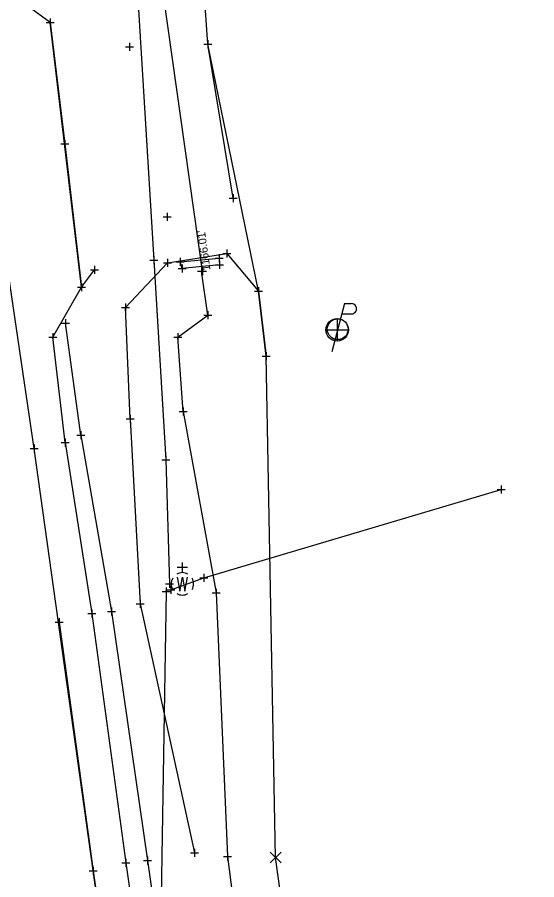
# Model space of a CAD drawing. Extents: x 2324380 to 2325559, y 691096 to 693386.
# Drawn here: x 2325205.9 to 2325270.8, y 691550.8 to 691658.5 of the extents above; entities that cross this region are included whole.
import ezdxf

# ---------------------------------------------------------------- set-up
doc = ezdxf.new("R2010")
doc.units = 0
for name, color, linetype in [('DR_X_Elev_Flow', 7, 'Continuous'), ('DR_X_Headwall', 7, 'Continuous'), ('DR_X_Storm_Sewer', 7, 'Continuous'), ('PM_X_Transverse_Line', 7, 'Continuous'), ('PV_X_Driveway', 7, 'Continuous'), ('PV_X_EOP', 7, 'Continuous'), ('PV_X_Shoulder_Aggregate', 7, 'Continuous'), ('SC_Scratch1', 7, 'Continuous'), ('SV_X_Control_Cells_Found', 7, 'Continuous'), ('SV_X_Random_Point', 7, 'Continuous'), ('SV_X_Shot_Marker', 7, 'Continuous'), ('SV_X_Terrain_Boundary', 7, 'Continuous'), ('SV_X_Toe_of_Slope', 7, 'Continuous'), ('SV_X_Top_of_Bank', 7, 'Continuous'), ('UT_X_Electric_Cells', 7, 'Continuous'), ('UT_X_Water', 7, 'Continuous'), ('UT_X_Water_Cells', 7, 'Continuous')]:
    doc.layers.add(name, color=color, linetype=linetype)

msp = doc.modelspace()

# ---------------------------------------------------------------- linework, layer by layer
at = {"layer": 'DR_X_Elev_Flow'}
for p, q in [((2325229.09, 691627.27), (2325229.09, 691626.27)), ((2325228.59, 691626.77), (2325229.59, 691626.77)), ((2325229.09, 691626.77), (2325229.09, 691626.77))]:
    msp.add_line(p, q, dxfattribs=at)
at = {"layer": 'DR_X_Headwall'}
msp.add_lwpolyline([(2325231.15, 691628.41), (2325231.2, 691627.58), (2325226.52, 691627.12), (2325226.3, 691627.96)], close=True, dxfattribs=at)
at = {"layer": 'DR_X_Storm_Sewer'}
msp.add_line((2325229.09, 691626.77), (2325217.52, 691708.33), dxfattribs=at)
at = {"layer": 'PM_X_Transverse_Line'}
for points in [[(2325208.03, 691604.62), (2325194.77, 691694.59), (2325190.22, 691721.35), (2325186.04, 691748.47), (2325180.66, 691777.72), (2325175.44, 691810.81), (2325170.12, 691836.61), (2325164.91, 691862.73), (2325159.59, 691887.99), (2325154.32, 691913.69), (2325148, 691940.38), (2325141.01, 691970.75), (2325134.25, 691997.6), (2325126.61, 692026.24), (2325119.99, 692049.57), (2325112.24, 692077.64)], [(2325211.18, 691582.94), (2325215.4, 691551.9), (2325219.83, 691521.11), (2325223.47, 691495.08), (2325231.47, 691437.85), (2325235.46, 691407.56), (2325239.99, 691376.18), (2325243.53, 691349.64), (2325247.32, 691323.83), (2325208.03, 691604.62)]]:
    msp.add_lwpolyline(points, dxfattribs=at)
at = {"layer": 'PV_X_Driveway'}
for p, q in [((2325210.03, 691657.83), (2325211.87, 691642.67)), ((2325232.92, 691635.92), (2325229.73, 691655.12)), ((2325211.87, 691642.67), (2325213.96, 691624.8)), ((2325213.96, 691624.8), (2325215.58, 691626.95))]:
    msp.add_line(p, q, dxfattribs=at)
at = {"layer": 'PV_X_EOP'}
for points in [[(2325211.92, 691605.39), (2325210.37, 691618.55), (2325213.96, 691624.8), (2325210.03, 691657.83), (2325203.56, 691662.57), (2325202.33, 691668.93), (2325198.24, 691695.48), (2325193.91, 691721.99), (2325189.38, 691749.91), (2325184.43, 691778.63), (2325178.88, 691811.26), (2325173.94, 691837.31), (2325168.71, 691863.96), (2325163.82, 691888.36), (2325158.39, 691913.65), (2325152.29, 691941.35), (2325145.12, 691971.33), (2325138.19, 691997.21), (2325140.74, 692005.58), (2325134.93, 692029.17), (2325130.4, 692046.73), (2325123.25, 692051.46), (2325115.82, 692078.51)], [(2325211.92, 691605.39), (2325215.25, 691584.03), (2325219.49, 691552.88), (2325224.03, 691521.29), (2325227.5, 691495.17), (2325231.22, 691468.2), (2325235.39, 691438.82), (2325239.64, 691407.75), (2325243.92, 691377.46), (2325247.9, 691350.92), (2325251.27, 691324.43)]]:
    msp.add_lwpolyline(points, dxfattribs=at)
at = {"layer": 'PV_X_Shoulder_Aggregate'}
for points in [[(2325213.88, 691606.29), (2325211.98, 691620.27)], [(2325213.88, 691606.29), (2325217.7, 691584.26), (2325222.21, 691553.19), (2325226.65, 691521.82), (2325230.46, 691495.18), (2325234, 691469.07), (2325237.48, 691439.41), (2325242.52, 691408.67), (2325246.13, 691377.89), (2325250.02, 691351.19), (2325253.28, 691324.76)]]:
    msp.add_lwpolyline(points, dxfattribs=at)
at = {"layer": 'SV_X_Control_Cells_Found'}
for p, q in [((2325245.89, 691620.86), (2325245.89, 691618.04)), ((2325244.48, 691619.45), (2325247.3, 691619.45))]:
    msp.add_line(p, q, dxfattribs=at)
msp.add_circle((2325245.89, 691619.45), 1.41, dxfattribs=at)
at = {"layer": 'SV_X_Random_Point'}
for p, q in [((2325237.54, 691552.88), (2325238.88, 691554.21)), ((2325237.54, 691554.21), (2325238.88, 691552.88))]:
    msp.add_line(p, q, dxfattribs=at)
at = {"layer": 'SV_X_Shot_Marker'}
for p, q in [((2325209.53, 691657.83), (2325210.53, 691657.83)), ((2325209.53, 691657.83), (2325210.53, 691657.83)), ((2325210.03, 691658.33), (2325210.03, 691657.33)), ((2325210.03, 691658.33), (2325210.03, 691657.33)), ((2325210.03, 691657.83), (2325210.03, 691657.83)), ((2325210.03, 691657.83), (2325210.03, 691657.83)), ((2325219.96, 691655.3), (2325219.96, 691654.3)), ((2325229.23, 691655.12), (2325230.23, 691655.12)), ((2325229.73, 691655.62), (2325229.73, 691654.62)), ((2325229.73, 691655.12), (2325229.73, 691655.12)), ((2325219.46, 691654.8), (2325220.46, 691654.8)), ((2325219.96, 691654.8), (2325219.96, 691654.8)), ((2325211.37, 691642.67), (2325212.37, 691642.67)), ((2325211.87, 691643.17), (2325211.87, 691642.17)), ((2325211.87, 691642.67), (2325211.87, 691642.67)), ((2325232.42, 691635.92), (2325233.42, 691635.92)), ((2325232.92, 691636.42), (2325232.92, 691635.42)), ((2325232.92, 691635.92), (2325232.92, 691635.92)), ((2325224.15, 691633.58), (2325225.15, 691633.58)), ((2325224.65, 691634.08), (2325224.65, 691633.08)), ((2325224.65, 691633.58), (2325224.65, 691633.58)), ((2325232.12, 691629.48), (2325232.12, 691628.48)), ((2325222.98, 691628.67), (2325222.98, 691627.67)), ((2325224.7, 691628.31), (2325224.7, 691627.31)), ((2325226.3, 691628.46), (2325226.3, 691627.46)), ((2325230.65, 691628.41), (2325231.65, 691628.41)), ((2325231.15, 691628.91), (2325231.15, 691627.91)), ((2325231.15, 691628.41), (2325231.15, 691628.41)), ((2325231.62, 691628.98), (2325232.62, 691628.98)), ((2325232.12, 691628.98), (2325232.12, 691628.98)), ((2325215.58, 691627.45), (2325215.58, 691626.45)), ((2325222.48, 691628.17), (2325223.48, 691628.17)), ((2325222.98, 691628.17), (2325222.98, 691628.17)), ((2325224.2, 691627.81), (2325225.2, 691627.81)), ((2325224.7, 691627.81), (2325224.7, 691627.81)), ((2325225.8, 691627.96), (2325226.8, 691627.96)), ((2325226.02, 691627.12), (2325227.02, 691627.12)), ((2325226.3, 691627.96), (2325226.3, 691627.96)), ((2325226.52, 691627.62), (2325226.52, 691626.62)), ((2325226.52, 691627.12), (2325226.52, 691627.12)), ((2325228.93, 691627.28), (2325228.93, 691626.28)), ((2325230.7, 691627.58), (2325231.7, 691627.58)), ((2325231.2, 691628.08), (2325231.2, 691627.08)), ((2325231.2, 691627.58), (2325231.2, 691627.58)), ((2325215.08, 691626.95), (2325216.08, 691626.95)), ((2325215.58, 691626.95), (2325215.58, 691626.95)), ((2325228.43, 691626.78), (2325229.43, 691626.78)), ((2325228.93, 691626.78), (2325228.93, 691626.78)), ((2325213.96, 691625.3), (2325213.96, 691624.3)), ((2325213.96, 691625.3), (2325213.96, 691624.3)), ((2325213.46, 691624.8), (2325214.46, 691624.8)), ((2325213.46, 691624.8), (2325214.46, 691624.8)), ((2325213.96, 691624.8), (2325213.96, 691624.8)), ((2325213.96, 691624.8), (2325213.96, 691624.8)), ((2325235.56, 691624.28), (2325236.56, 691624.28)), ((2325236.06, 691624.78), (2325236.06, 691623.78)), ((2325236.06, 691624.28), (2325236.06, 691624.28)), ((2325218.95, 691622.24), (2325219.95, 691622.24)), ((2325219.45, 691622.74), (2325219.45, 691621.74)), ((2325219.45, 691622.24), (2325219.45, 691622.24)), ((2325229.72, 691621.77), (2325229.72, 691620.77)), ((2325211.98, 691620.77), (2325211.98, 691619.77)), ((2325229.22, 691621.27), (2325230.22, 691621.27)), ((2325229.72, 691621.27), (2325229.72, 691621.27)), ((2325211.48, 691620.27), (2325212.48, 691620.27)), ((2325211.98, 691620.27), (2325211.98, 691620.27)), ((2325209.87, 691618.55), (2325210.87, 691618.55)), ((2325210.37, 691619.05), (2325210.37, 691618.05)), ((2325210.37, 691618.55), (2325210.37, 691618.55)), ((2325225.48, 691618.53), (2325226.48, 691618.53)), ((2325225.98, 691619.03), (2325225.98, 691618.03)), ((2325225.98, 691618.53), (2325225.98, 691618.53)), ((2325237.01, 691616.67), (2325237.01, 691615.67)), ((2325236.51, 691616.17), (2325237.51, 691616.17)), ((2325237.01, 691616.17), (2325237.01, 691616.17)), ((2325220.04, 691608.83), (2325220.04, 691607.83)), ((2325226.16, 691609.25), (2325227.16, 691609.25)), ((2325226.66, 691609.75), (2325226.66, 691608.75)), ((2325226.66, 691609.25), (2325226.66, 691609.25)), ((2325219.54, 691608.33), (2325220.54, 691608.33)), ((2325220.04, 691608.33), (2325220.04, 691608.33)), ((2325213.88, 691606.79), (2325213.88, 691605.79)), ((2325211.92, 691605.89), (2325211.92, 691604.89)), ((2325213.38, 691606.29), (2325214.38, 691606.29)), ((2325213.88, 691606.29), (2325213.88, 691606.29)), ((2325207.53, 691604.62), (2325208.53, 691604.62)), ((2325208.03, 691605.12), (2325208.03, 691604.12)), ((2325208.03, 691604.62), (2325208.03, 691604.62)), ((2325211.42, 691605.39), (2325212.42, 691605.39)), ((2325211.92, 691605.39), (2325211.92, 691605.39)), ((2325224.5, 691603.72), (2325224.5, 691602.72)), ((2325224, 691603.22), (2325225, 691603.22)), ((2325224.5, 691603.22), (2325224.5, 691603.22)), ((2325265.86, 691599.52), (2325266.86, 691599.52)), ((2325266.36, 691600.02), (2325266.36, 691599.02)), ((2325266.36, 691599.52), (2325266.36, 691599.52)), ((2325228.73, 691588.49), (2325229.73, 691588.49)), ((2325229.23, 691588.99), (2325229.23, 691587.99)), ((2325229.23, 691588.49), (2325229.23, 691588.49)), ((2325224.47, 691587.75), (2325225.47, 691587.75)), ((2325224.54, 691587.27), (2325224.54, 691586.27)), ((2325224.97, 691588.25), (2325224.97, 691587.25)), ((2325224.97, 691587.75), (2325224.97, 691587.75)), ((2325225.1, 691587.48), (2325225.1, 691586.48)), ((2325224.04, 691586.77), (2325225.04, 691586.77)), ((2325224.54, 691586.77), (2325224.54, 691586.77)), ((2325224.6, 691586.98), (2325225.6, 691586.98)), ((2325225.1, 691586.98), (2325225.1, 691586.98)), ((2325230.29, 691586.61), (2325231.29, 691586.61)), ((2325230.79, 691587.11), (2325230.79, 691586.11)), ((2325230.79, 691586.61), (2325230.79, 691586.61)), ((2325220.78, 691585.23), (2325221.78, 691585.23)), ((2325221.28, 691585.73), (2325221.28, 691584.73)), ((2325221.28, 691585.23), (2325221.28, 691585.23)), ((2325214.75, 691584.03), (2325215.75, 691584.03)), ((2325215.25, 691584.53), (2325215.25, 691583.53)), ((2325215.25, 691584.03), (2325215.25, 691584.03)), ((2325217.2, 691584.26), (2325218.2, 691584.26)), ((2325217.7, 691584.76), (2325217.7, 691583.76)), ((2325217.7, 691584.26), (2325217.7, 691584.26)), ((2325210.68, 691582.94), (2325211.68, 691582.94)), ((2325211.18, 691583.44), (2325211.18, 691582.44)), ((2325211.18, 691582.94), (2325211.18, 691582.94)), ((2325227.57, 691554.15), (2325228.57, 691554.15)), ((2325228.07, 691554.65), (2325228.07, 691553.65)), ((2325228.07, 691554.15), (2325228.07, 691554.15)), ((2325232.18, 691554.17), (2325232.18, 691553.17)), ((2325218.99, 691552.88), (2325219.99, 691552.88)), ((2325219.49, 691553.38), (2325219.49, 691552.38)), ((2325219.49, 691552.88), (2325219.49, 691552.88)), ((2325221.71, 691553.19), (2325222.71, 691553.19)), ((2325222.21, 691553.69), (2325222.21, 691552.69)), ((2325222.21, 691553.19), (2325222.21, 691553.19)), ((2325231.68, 691553.67), (2325232.68, 691553.67)), ((2325232.18, 691553.67), (2325232.18, 691553.67)), ((2325214.9, 691551.9), (2325215.9, 691551.9)), ((2325215.4, 691552.4), (2325215.4, 691551.4)), ((2325215.4, 691551.9), (2325215.4, 691551.9))]:
    msp.add_line(p, q, dxfattribs=at)
at = {"layer": 'SV_X_Terrain_Boundary'}
msp.add_lwpolyline([(2325246.03, 691497.72), (2325238.21, 691553.54), (2325237.01, 691616.17), (2325236.06, 691624.28), (2325229.73, 691655.12), (2325225.64, 691713.9), (2325265.08, 691838.33), (2325358.67, 691858.64)], dxfattribs=at)
at = {"layer": 'SV_X_Toe_of_Slope'}
for points in [[(2325226.66, 691609.25), (2325225.98, 691618.53), (2325229.72, 691621.27), (2325228.93, 691626.78)], [(2325226.66, 691609.25), (2325230.79, 691586.61), (2325232.18, 691553.67), (2325236.09, 691523.17), (2325239.94, 691497.82), (2325240.19, 691470.77), (2325244.87, 691439.56), (2325246.92, 691409.95), (2325249.5, 691377.94), (2325253.11, 691351.77), (2325256.85, 691325.16)]]:
    msp.add_lwpolyline(points, dxfattribs=at)
at = {"layer": 'SV_X_Top_of_Bank'}
for points in [[(2325220.04, 691608.33), (2325219.45, 691622.24), (2325224.7, 691627.81), (2325232.12, 691628.98), (2325236.06, 691624.28), (2325237.01, 691616.17)], [(2325220.04, 691608.33), (2325221.28, 691585.23), (2325228.07, 691554.15)]]:
    msp.add_lwpolyline(points, dxfattribs=at)
at = {"layer": 'UT_X_Electric_Cells'}
for p, q in [((2325246.81, 691622.73), (2325245.21, 691616.73)), ((2325246.81, 691622.73), (2325247.66, 691622.73)), ((2325246.47, 691621.45), (2325247.66, 691621.45))]:
    msp.add_line(p, q, dxfattribs=at)
msp.add_circle((2325245.96, 691619.53), 1.3, dxfattribs=at)
msp.add_arc((2325247.68, 691622.09), 0.638, 268.8767, 91.1233, dxfattribs=at)
at = {"layer": 'UT_X_Water'}
for points in [[(2325124.52, 692091.67), (2325134.64, 692057.74), (2325147.68, 692015.89), (2325157.51, 691980.18), (2325171.32, 691933.62), (2325182.7, 691894.58), (2325195.31, 691848.43), (2325206.62, 691806.01), (2325210.43, 691786.81), (2325214.15, 691760.19), (2325217.41, 691715.9), (2325220.6, 691667.67), (2325222.98, 691628.17), (2325224.5, 691603.22), (2325224.97, 691587.75)], [(2325225.1, 691586.98), (2325229.23, 691588.49), (2325266.36, 691599.52)], [(2325224.54, 691586.77), (2325223.34, 691513.04), (2325228.73, 691469.8), (2325235.04, 691419.71), (2325241.96, 691370.73), (2325247.23, 691328.41), (2325252.34, 691287.68), (2325258.98, 691247.22)]]:
    msp.add_lwpolyline(points, dxfattribs=at)
at = {"layer": 'UT_X_Water_Cells'}
for p, q in [((2325227.19, 691589.77), (2325225.92, 691589.77)), ((2325226.56, 691589.13), (2325226.56, 691590.4)), ((2325226.56, 691587.73), (2325226.56, 691587.73))]:
    msp.add_line(p, q, dxfattribs=at)
msp.add_lwpolyline([(2325225.92, 691588.55), (2325226.24, 691586.83), (2325226.56, 691588.55), (2325226.88, 691586.83), (2325227.19, 691588.55)], dxfattribs=at)
for start, end in [(150.0184, 209.9816), (60.0184, 120.0157), (330.0184, 29.9816), (239.9843, 299.9816)]:
    msp.add_arc((2325226.56, 691587.73), 1.4, start, end, dxfattribs=at)

# ---------------------------------------------------------------- texts
at = {"layer": 'SC_Scratch1'}
msp.add_text("1166.01'", height=1, rotation=98.0692, dxfattribs=at).set_placement((2325230.08, 691626.91))

doc.saveas('drawing.dxf')
